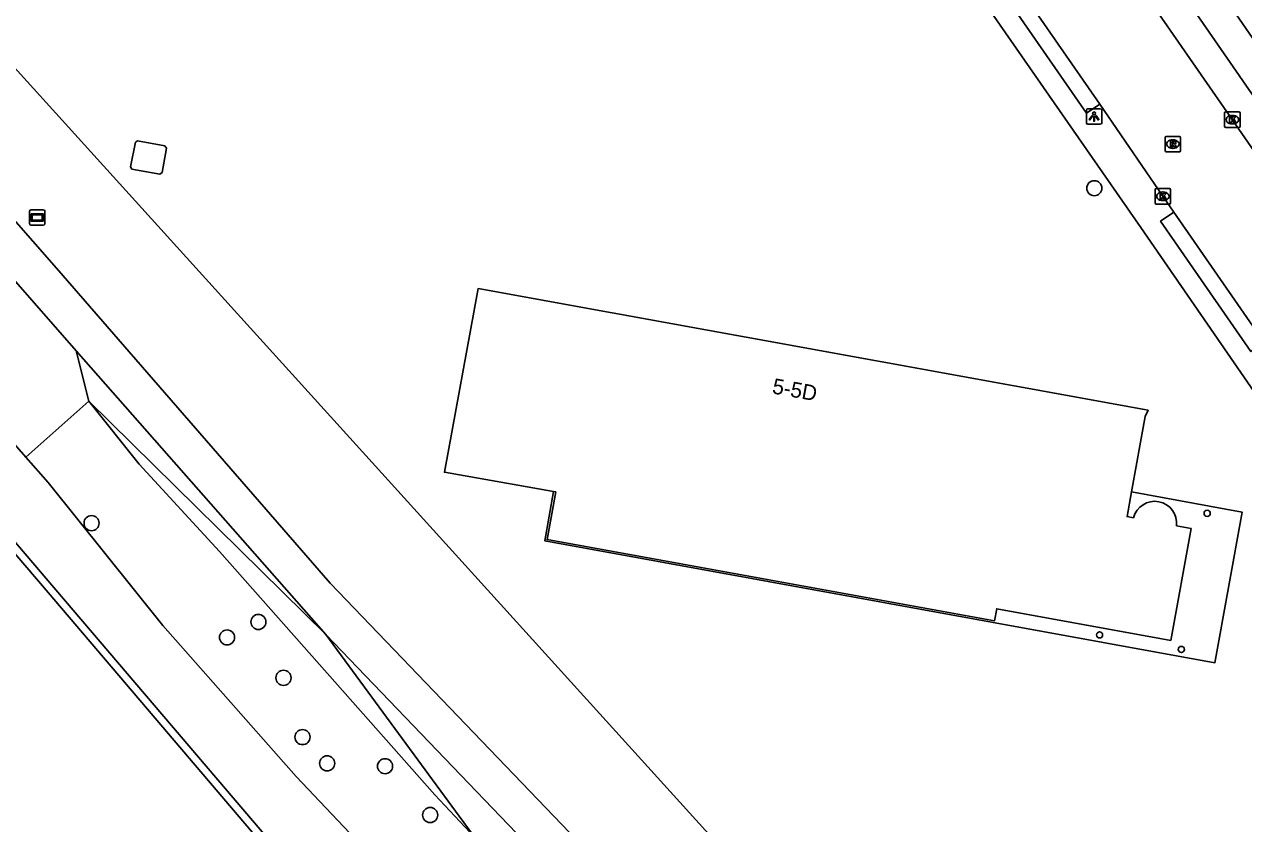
# Model space of a CAD drawing. Extents: x 157466 to 158888, y 383063 to 384677.
# Drawn here: x 157837.3 to 157916.4, y 383309.5 to 383361.3 of the extents above; entities that cross this region are included whole.
import ezdxf

# ---------------------------------------------------------------- set-up
doc = ezdxf.new("R2010")
doc.units = 0
for name, color, linetype in [('IMGEO_Boom', 7, 'Continuous'), ('IMGEO_Groenvoorziening', 7, 'Continuous'), ('IMGEO_Hek', 7, 'Continuous'), ('IMGEO_Kademuur', 7, 'Continuous'), ('IMGEO_Kolk', 7, 'Continuous'), ('IMGEO_Lage_trafo', 7, 'Continuous'), ('IMGEO_Lichtpunt', 7, 'Continuous'), ('IMGEO_Pand', 7, 'Continuous'), ('IMGEO_Pand_nummerreeks', 7, 'Continuous'), ('IMGEO_Pand_overbouw', 7, 'Continuous'), ('IMGEO_Rijbaan_lokaal_open', 7, 'Continuous'), ('IMGEO_Rioolput', 7, 'Continuous'), ('IMGEO_Verklikker', 7, 'Continuous'), ('IMGEO_Voetpad_open', 7, 'Continuous')]:
    doc.layers.add(name, color=color, linetype=linetype)

msp = doc.modelspace()

# ---------------------------------------------------------------- linework, layer by layer
at = {"layer": 'IMGEO_Boom'}
for centre in [(157906.68, 383350.678), (157841.696, 383328.967), (157852.507, 383322.562), (157850.476, 383321.561), (157854.135, 383318.939), (157855.368, 383315.097), (157856.961, 383313.396), (157860.715, 383313.208), (157863.638, 383310.047)]:
    msp.add_circle(centre, 0.489, dxfattribs=at)
at = {"layer": 'IMGEO_Groenvoorziening'}
for points in [[(157793.514, 383406.385), (157803.74, 383395.36), (157805.588, 383392.998), (157807.532, 383390.715), (157849.702, 383344.141), (157889.589, 383300.088), (157949.885, 383232.91)], [(157840.702, 383340.129), (157819.868, 383363.95), (157790.961, 383396.646), (157792.897, 383398.29)], [(157948.97, 383232.31), (157933.282, 383250), (157922.54, 383262.113), (157912.574, 383272.677), (157895.75, 383287.54), (157892.353, 383290.294), (157878.365, 383302.971), (157857.156, 383325.085), (157844.559, 383339.577), (157839.418, 383345.491), (157821.749, 383365.653), (157792.897, 383398.29)], [(157837.43, 383333.25), (157828.189, 383343.803), (157823.46, 383348.301), (157819.505, 383352.478), (157813.418, 383359.649), (157810.105, 383364.184), (157809.454, 383365.749), (157808.496, 383367.377), (157798.024, 383376.429), (157790.857, 383384.564), (157788.138, 383388.239), (157788.135, 383388.897), (157788.491, 383389.582)], [(157841.52, 383336.879), (157840.702, 383340.129)], [(157840.702, 383340.129), (157856.871, 383321.74)], [(157837.43, 383333.25), (157841.52, 383336.879)], [(157841.52, 383336.879), (157856.871, 383321.74)], [(157841.52, 383336.879), (157844.77, 383332.795), (157849.981, 383327.129), (157863.939, 383311.349), (157866.539, 383308.593)], [(157885.528, 383284.108), (157887.593, 383281.168), (157893.63, 383272.831), (157901.188, 383262.739), (157906.995, 383254.443), (157915.529, 383245.154), (157918.267, 383241.049), (157922.86, 383234.47), (157926.842, 383225.106), (157917.651, 383237.226), (157908.535, 383248.235), (157901.575, 383256.835), (157894.788, 383265.544), (157888.045, 383273.242), (157884.324, 383277.835), (157881.179, 383281.998), (157879.083, 383284.208), (157877.055, 383287.129), (157866.336, 383300.067), (157859.97, 383307.251), (157854.953, 383312.545), (157846.321, 383322.336), (157838.876, 383331.598), (157837.43, 383333.25)], [(157877.178, 383300.624), (157876.952, 383300.826), (157856.871, 383321.74)], [(157856.871, 383321.74), (157866.539, 383308.593)]]:
    msp.add_lwpolyline(points, dxfattribs=at)
at = {"layer": 'IMGEO_Hek'}
for points in [[(157849.702, 383344.141), (157807.532, 383390.715), (157805.588, 383392.998), (157803.74, 383395.36), (157793.514, 383406.385)], [(157889.589, 383300.088), (157849.702, 383344.141)]]:
    msp.add_lwpolyline(points, dxfattribs=at)
at = {"layer": 'IMGEO_Kademuur'}
for points in [[(157914.241, 383237.382), (157915.119, 383236.379), (157914.743, 383236.05), (157899.566, 383253.379), (157896.454, 383257.066), (157887.441, 383267.609), (157876.661, 383280.152), (157866.203, 383292.293), (157853.494, 383307.318), (157838.382, 383325.044), (157833.403, 383330.862), (157827.253, 383337.957), (157811.612, 383356.218), (157808.232, 383360.334), (157808.039, 383360.562), (157808.417, 383360.89)], [(157808.601, 383360.672), (157808.618, 383360.651), (157811.995, 383356.539), (157827.632, 383338.283), (157833.781, 383331.188), (157838.763, 383325.368), (157853.875, 383307.642), (157866.583, 383292.617), (157877.04, 383280.478), (157887.821, 383267.935), (157896.835, 383257.389), (157899.945, 383253.705), (157912.362, 383239.528)]]:
    msp.add_lwpolyline(points, dxfattribs=at)
at = {"layer": 'IMGEO_Kolk'}
for p, q in [((157915.124, 383354.696), (157915.124, 383355.548)), ((157915.199, 383355.622), (157916.051, 383355.622)), ((157915.612, 383355.402), (157915.637, 383355.402)), ((157916.125, 383355.548), (157916.125, 383354.696)), ((157916.051, 383354.622), (157915.199, 383354.622)), ((157915.635, 383354.842), (157915.61, 383354.842)), ((157910.62, 383349.728), (157910.62, 383350.58)), ((157910.695, 383350.654), (157911.547, 383350.654)), ((157911.621, 383350.58), (157911.621, 383349.728)), ((157911.131, 383349.874), (157911.106, 383349.874)), ((157911.108, 383350.434), (157911.133, 383350.434)), ((157911.547, 383349.654), (157910.695, 383349.654))]:
    msp.add_line(p, q, dxfattribs=at)
for points in [[(157915.124, 383354.696), (157915.124, 383355.548)], [(157915.199, 383355.622), (157916.051, 383355.622)], [(157915.445, 383355.322), (157915.568, 383355.322), (157915.568, 383355.171), (157915.698, 383355.322), (157915.862, 383355.322), (157915.716, 383355.171), (157915.869, 383354.922), (157915.717, 383354.922), (157915.632, 383355.086), (157915.568, 383355.019), (157915.568, 383354.922), (157915.445, 383354.922), (157915.445, 383355.322)], [(157916.125, 383355.548), (157916.125, 383354.696)], [(157916.051, 383354.622), (157915.199, 383354.622)], [(157910.62, 383349.728), (157910.62, 383350.58)], [(157910.695, 383350.654), (157911.547, 383350.654)], [(157911.621, 383350.58), (157911.621, 383349.728)], [(157910.941, 383350.354), (157911.064, 383350.354), (157911.064, 383350.203), (157911.194, 383350.354), (157911.358, 383350.354), (157911.212, 383350.203), (157911.365, 383349.954), (157911.213, 383349.954), (157911.128, 383350.118), (157911.064, 383350.051), (157911.064, 383349.954), (157910.941, 383349.954), (157910.941, 383350.354)], [(157911.547, 383349.654), (157910.695, 383349.654)]]:
    msp.add_lwpolyline(points, dxfattribs=at)
for centre, start, end in [((157915.201, 383355.546), 91.55205, 178.44795), ((157915.201, 383355.546), 91.55205, 178.44795), ((157916.049, 383355.546), 1.55205, 88.44795), ((157916.049, 383355.546), 1.55205, 88.44795), ((157915.201, 383354.698), 181.55205, 268.44795), ((157915.201, 383354.698), 181.55205, 268.44795), ((157916.049, 383354.698), 271.55205, 358.44795), ((157916.049, 383354.698), 271.55205, 358.44795), ((157910.697, 383350.578), 91.55205, 178.44795), ((157910.697, 383350.578), 91.55205, 178.44795), ((157911.545, 383350.578), 1.55205, 88.44795), ((157911.545, 383350.578), 1.55205, 88.44795), ((157910.697, 383349.73), 181.55205, 268.44795), ((157910.697, 383349.73), 181.55205, 268.44795), ((157911.545, 383349.73), 271.55205, 358.44795), ((157911.545, 383349.73), 271.55205, 358.44795)]:
    msp.add_arc(centre, 0.0765, start, end, dxfattribs=at)
for centre, major_axis, ratio, start_param, end_param in [((157915.611, 383355.122), (-0.387, 0.002), 0.722429, 4.712389, 7.853982), ((157915.636, 383355.122), (-0.39, 0.002), 0.717154, 1.570796, 4.712389), ((157911.107, 383350.154), (-0.387, 0.002), 0.722429, 4.712389, 7.853982), ((157911.132, 383350.154), (-0.39, 0.002), 0.717154, 1.570796, 4.712389)]:
    msp.add_ellipse(centre, major_axis=major_axis, ratio=ratio, start_param=start_param, end_param=end_param, dxfattribs=at)
at = {"layer": 'IMGEO_Lage_trafo'}
msp.add_lwpolyline([(157846.113, 383351.597), (157846.262, 383351.692), (157846.561, 383353.282), (157846.434, 383353.431), (157844.666, 383353.744), (157844.534, 383353.659), (157844.217, 383352.067), (157844.307, 383351.917), (157846.113, 383351.597)], dxfattribs=at)
at = {"layer": 'IMGEO_Lichtpunt'}
for p, q in [((157906.166, 383355.726), (157906.166, 383354.919)), ((157906.166, 383355.726), (157906.166, 383354.919)), ((157907.068, 383355.821), (157906.26, 383355.821)), ((157907.068, 383355.821), (157906.26, 383355.821)), ((157907.162, 383354.919), (157907.162, 383355.726)), ((157907.162, 383354.919), (157907.162, 383355.726)), ((157906.26, 383354.825), (157907.068, 383354.825)), ((157906.26, 383354.825), (157907.068, 383354.825))]:
    msp.add_line(p, q, dxfattribs=at)
for points in [[(157906.54, 383355.39), (157906.579, 383355.362), (157906.391, 383355.1), (157906.353, 383355.127), (157906.54, 383355.39)], [(157906.642, 383355.342), (157906.689, 383355.342), (157906.689, 383355.02), (157906.642, 383355.02), (157906.642, 383355.342)], [(157906.752, 383355.362), (157906.79, 383355.389), (157906.977, 383355.127), (157906.938, 383355.099), (157906.752, 383355.362)]]:
    msp.add_lwpolyline(points, dxfattribs=at)
msp.add_circle((157906.665, 383355.524), 0.0994, dxfattribs=at)
for centre, start, end in [((157906.26, 383355.726), 90, 180), ((157906.26, 383355.726), 90, 180), ((157907.068, 383355.726), 0, 90), ((157907.068, 383355.726), 0, 90), ((157906.26, 383354.919), 180, 270), ((157906.26, 383354.919), 180, 270), ((157907.068, 383354.919), 270, 0), ((157907.068, 383354.919), 270, 360)]:
    msp.add_arc(centre, 0.0946, start, end, dxfattribs=at)
at = {"layer": 'IMGEO_Pand'}
msp.add_lwpolyline([(157909.219, 383329.321), (157908.806, 383329.395), (157909.096, 383330.992), (157909.984, 383335.877), (157910.161, 383336.285), (157866.745, 383344.174), (157864.564, 383332.268), (157871.636, 383331.013), (157871.774, 383330.989), (157871.213, 383327.905), (157900.211, 383322.635), (157900.354, 383323.422), (157911.634, 383321.36), (157912.951, 383328.611), (157911.997, 383328.784)], dxfattribs=at)
for centre, radius, start, end in [((157910.591, 383328.964), 1.418, 352.6968, 165.42201), ((157913.993, 383329.608), 0.2, 0, 180), ((157913.993, 383329.608), 0.2, 180, 0), ((157907.019, 383321.725), 0.2, 0, 180), ((157907.019, 383321.725), 0.2, 180, 360), ((157912.321, 383320.781), 0.2, 0, 180), ((157912.321, 383320.781), 0.2, 180, 0)]:
    msp.add_arc(centre, radius, start, end, dxfattribs=at)
at = {"layer": 'IMGEO_Pand_overbouw'}
for points in [[(157911.997, 383328.784), (157912.951, 383328.611), (157911.634, 383321.36), (157900.354, 383323.422), (157900.211, 383322.635), (157871.213, 383327.905), (157871.774, 383330.989), (157871.636, 383331.013), (157871.064, 383327.83), (157914.492, 383319.917), (157916.251, 383329.679), (157909.096, 383330.992)], [(157909.096, 383330.992), (157908.806, 383329.395), (157909.219, 383329.321)]]:
    msp.add_lwpolyline(points, dxfattribs=at)
msp.add_arc((157910.591, 383328.964), 1.418, 352.6968, 165.42201, dxfattribs=at)
at = {"layer": 'IMGEO_Rijbaan_lokaal_open'}
for points in [[(157936.465, 383325.145), (157935.643, 383326.174), (157935.388, 383326.53), (157915.623, 383355.122), (157905.565, 383369.639), (157894.321, 383385.972), (157880.805, 383405.562), (157871.979, 383418.406), (157863.862, 383430.224), (157863.215, 383431.182)], [(157900.174, 383366.038), (157907.035, 383356.127)], [(157907.035, 383356.127), (157911.123, 383350.155), (157911.832, 383349.127)], [(157911.832, 383349.127), (157917.679, 383340.677)]]:
    msp.add_lwpolyline(points, dxfattribs=at)
at = {"layer": 'IMGEO_Rioolput'}
for p, q in [((157911.27, 383353.114), (157911.27, 383353.966)), ((157911.345, 383354.04), (157912.197, 383354.04)), ((157911.758, 383353.82), (157911.783, 383353.82)), ((157912.271, 383353.966), (157912.271, 383353.114)), ((157912.197, 383353.04), (157911.345, 383353.04)), ((157911.781, 383353.26), (157911.756, 383353.26))]:
    msp.add_line(p, q, dxfattribs=at)
for points in [[(157911.27, 383353.114), (157911.27, 383353.966)], [(157911.345, 383354.04), (157912.197, 383354.04)], [(157911.859, 383353.738), (157911.607, 383353.74), (157911.607, 383353.34)], [(157911.785, 383353.659), (157911.731, 383353.659), (157911.731, 383353.578)], [(157912.271, 383353.966), (157912.271, 383353.114)], [(157912.197, 383353.04), (157911.345, 383353.04)], [(157911.607, 383353.34), (157911.731, 383353.34), (157911.731, 383353.502), (157911.742, 383353.502)], [(157911.731, 383353.578), (157911.783, 383353.578)], [(157911.789, 383353.473), (157911.86, 383353.34), (157912, 383353.34), (157911.935, 383353.466)]]:
    msp.add_lwpolyline(points, dxfattribs=at)
for centre, radius, start, end in [((157911.347, 383353.964), 0.0765, 91.55205, 178.44795), ((157911.347, 383353.964), 0.0765, 91.55205, 178.44795), ((157911.791, 383353.563), 0.0964, 77.00612, 93.18647), ((157911.805, 383353.62), 0.0378, 276.66336, 79.67722), ((157911.858, 383353.628), 0.109, 350.36119, 89.41601), ((157912.195, 383353.964), 0.0765, 1.55205, 88.44795), ((157912.195, 383353.964), 0.0765, 1.55205, 88.44795), ((157911.347, 383353.116), 0.0765, 181.55205, 268.44795), ((157911.347, 383353.116), 0.0765, 181.55205, 268.44795), ((157911.741, 383353.449), 0.0533, 26.02933, 88.69889), ((157911.767, 383353.767), 0.19, 274.7715, 282.96867), ((157911.856, 383353.628), 0.112, 277.58423, 350.98172), ((157911.84, 383353.413), 0.108, 29.51342, 73.79051), ((157912.195, 383353.116), 0.0765, 271.55205, 358.44795), ((157912.195, 383353.116), 0.0765, 271.55205, 358.44795)]:
    msp.add_arc(centre, radius, start, end, dxfattribs=at)
for centre, major_axis, ratio, start_param, end_param in [((157911.757, 383353.54), (-0.387, 0.002), 0.722429, 4.712389, 7.853982), ((157911.782, 383353.54), (-0.39, 0.002), 0.717154, 1.570796, 4.712389)]:
    msp.add_ellipse(centre, major_axis=major_axis, ratio=ratio, start_param=start_param, end_param=end_param, dxfattribs=at)
at = {"layer": 'IMGEO_Verklikker'}
for p, q in [((157837.678, 383348.38), (157837.678, 383349.18)), ((157837.678, 383349.18), (157837.678, 383348.38)), ((157837.778, 383349.28), (157838.568, 383349.28)), ((157838.568, 383349.28), (157837.778, 383349.28)), ((157838.668, 383349.18), (157838.668, 383348.38)), ((157838.668, 383348.38), (157838.668, 383349.18)), ((157838.568, 383348.28), (157837.778, 383348.28)), ((157837.778, 383348.28), (157838.568, 383348.28))]:
    msp.add_line(p, q, dxfattribs=at)
for points in [[(157837.779, 383349.012), (157838.567, 383349.012), (157838.567, 383348.548), (157837.779, 383348.548), (157837.779, 383349.012)], [(157837.844, 383348.947), (157837.844, 383348.613), (157838.502, 383348.613), (157838.502, 383348.947), (157837.844, 383348.947)]]:
    msp.add_lwpolyline(points, dxfattribs=at)
for centre, start, end in [((157837.778, 383349.18), 90, 180), ((157837.778, 383349.18), 90, 180), ((157838.568, 383349.18), 0, 90), ((157838.568, 383349.18), 360, 90), ((157837.778, 383348.38), 180, 270), ((157837.778, 383348.38), 180, 270), ((157838.568, 383348.38), 270, 0), ((157838.568, 383348.38), 270, 0)]:
    msp.add_arc(centre, 0.1, start, end, dxfattribs=at)
at = {"layer": 'IMGEO_Voetpad_open'}
for points in [[(157939.64, 383327.608), (157908.666, 383372.402), (157867.433, 383432.258)], [(157877.163, 383395.127), (157877.384, 383395.064), (157877.36, 383394.852), (157881.344, 383389.058), (157886.267, 383381.935), (157886.385, 383381.901), (157890.311, 383376.164), (157895.075, 383369.235), (157898.462, 383364.319), (157909.683, 383348.132), (157925.669, 383324.951), (157928.425, 383320.955), (157932.838, 383314.613), (157951.478, 383311.189), (157955.59, 383314.069), (157957.186, 383314.977), (157965.542, 383320.73)], [(157890.489, 383394.989), (157907.044, 383371.058), (157936.153, 383328.952)], [(157907.035, 383356.127), (157906.18, 383355.535), (157899.319, 383365.446), (157900.174, 383366.038)], [(157917.679, 383340.677), (157916.824, 383340.085), (157910.977, 383348.535), (157911.832, 383349.127)]]:
    msp.add_lwpolyline(points, dxfattribs=at)

# ---------------------------------------------------------------- texts
at = {"layer": 'IMGEO_Pand_nummerreeks'}
msp.add_text('5-5D', height=1, rotation=349.70131, dxfattribs=at).set_placement((157885.759, 383337.385))

doc.saveas('drawing.dxf')
